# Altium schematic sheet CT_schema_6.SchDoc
size 254 x 245 mm
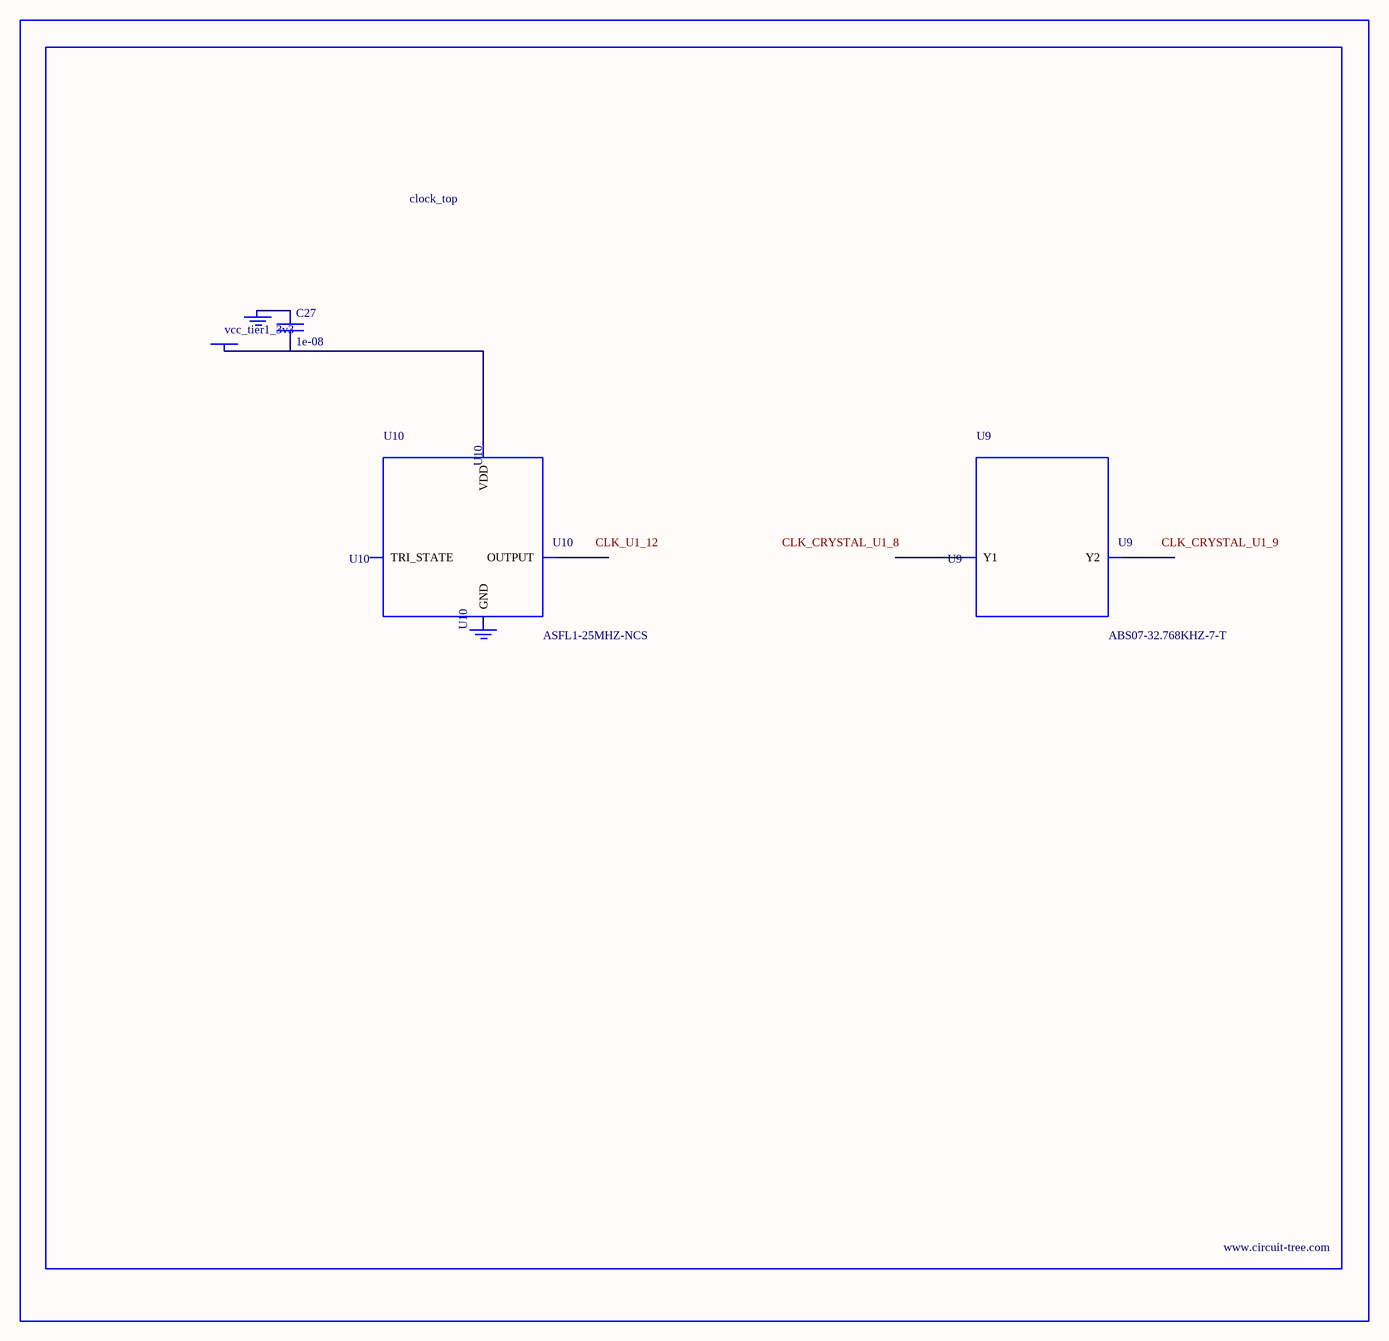
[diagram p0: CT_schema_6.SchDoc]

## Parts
BORDER5  (no value)
C27  1e-08  [C0402]
GND_INSTANCE_5_0  (no value)
GND_INSTANCE_5_1  (no value)
POWER_INSTANCE_5_0  vcc_tier1_3v3
U9  ABS07-32.768KHZ-7-T  [ABS07-32.768KHZ-7-T]
U10  ASFL1-25MHZ-NCS  [ASFL1]

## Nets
NetC27_1: C27.1 GND_INSTANCE_5_0.0(GND)
NetC27_2: C27.2 POWER_INSTANCE_5_0.0(PWR) U10.4(VDD)

Not connected (* = marked no-connect by the designer): GND_INSTANCE_5_1 0(GND); U9 1(Y1) 2(Y2); U10 1(TRI_STATE) 2(GND) 3(OUTPUT)

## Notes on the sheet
- Labels drawn without touching a wire or pin: CLK_CRYSTAL_U1_8, CLK_CRYSTAL_U1_9, CLK_U1_12

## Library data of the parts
BORDER5 = BORDER_PAGE5
C27 = C0402C103K3RAC
GND_INSTANCE_5_0 GND_INSTANCE_5_1 = GND
POWER_INSTANCE_5_0 = PWR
